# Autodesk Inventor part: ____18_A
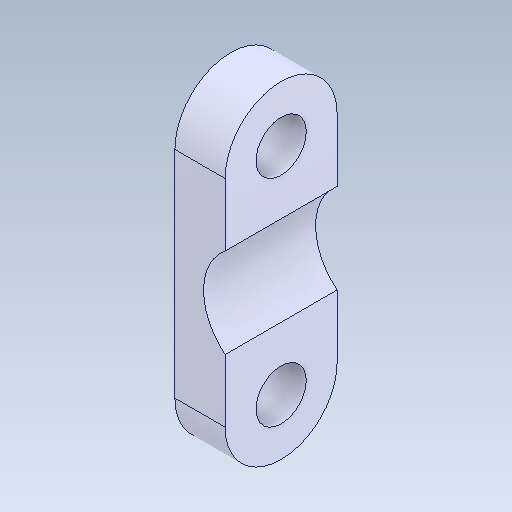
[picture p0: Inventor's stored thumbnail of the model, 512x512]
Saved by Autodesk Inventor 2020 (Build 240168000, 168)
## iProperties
Created: 2017-09
Part Number: ____18_A
Material: Générique
Document SubType Name: Modeling
Designer: bruno
Density: 1 g/cm^3
Appearance: Par défaut
Author: bruno
Sending System: SolidWorks 2016
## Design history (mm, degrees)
feature "Importée1"
node "Solide1"
